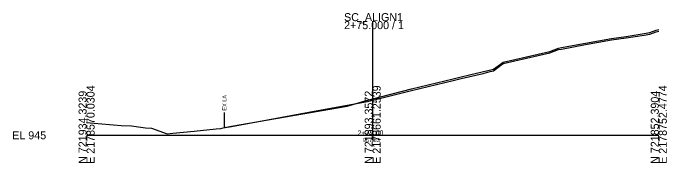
# Model space of a CAD drawing. Extents: x -2342 to 14913, y -10 to 5257.
# Drawn here: x 974.3 to 1202.8, y 490.3 to 542.8 of the extents above; entities that cross this region are included whole.
import ezdxf

# ---------------------------------------------------------------- set-up
doc = ezdxf.new("R2010")
doc.units = 0
for name, color, linetype in [('Default', 7, 'Continuous'), ('GK_Cells', 7, 'Continuous'), ('RW_X_Esmt_LA', 7, 'Continuous'), ('SC_Scratch1', 7, 'Continuous'), ('XS_P_Annotation', 7, 'Continuous'), ('XS_X_Ground_Line', 7, 'Continuous')]:
    doc.layers.add(name, color=color, linetype=linetype)

msp = doc.modelspace()

# ---------------------------------------------------------------- linework, layer by layer
at = {"layer": 'Default'}
msp.add_line((1048.2, 502.94), (1048.2, 502.69), dxfattribs=at)
at = {"layer": 'GK_Cells'}
for p, q in [((1100, 500), (1100, 540)), ((1000, 500), (1100, 500)), ((1100, 500), (1200, 500))]:
    msp.add_line(p, q, dxfattribs=at)
at = {"layer": 'RW_X_Esmt_LA'}
msp.add_line((1048.2, 502.94), (1048.2, 507.94), dxfattribs=at)
at = {"layer": 'SC_Scratch1'}
msp.add_lwpolyline([(1000, 504.49), (1003.92, 504.15), (1009.38, 503.69), (1012.09, 503.41), (1015.7, 503.27), (1020.63, 502.56), (1022.72, 502.51), (1028.16, 500.57), (1030.18, 500.74), (1037.65, 501.48), (1045.29, 502.21), (1046.79, 502.41), (1046.93, 502.43), (1047.79, 502.6), (1050.66, 503.11), (1080.82, 508.69), (1098.2, 511.83), (1100, 512.32), (1113.53, 515.73), (1128.09, 519.24), (1130.88, 519.92), (1138.57, 521.68), (1141.11, 522.37), (1142.18, 522.62), (1144.75, 524.57), (1145.59, 525.17), (1161.86, 528.87), (1164.98, 530.02), (1165.94, 530.23), (1174.38, 531.81), (1183.51, 533.42), (1188.58, 534.12), (1194.85, 535.12), (1196.82, 535.47), (1199.08, 536.29), (1200, 536.51)], dxfattribs=at)
at = {"layer": 'XS_X_Ground_Line'}
msp.add_lwpolyline([(1000, 504.49), (1003.92, 504.15), (1009.38, 503.69), (1012.09, 503.41), (1015.7, 503.27), (1020.63, 502.56), (1022.72, 502.51), (1028.16, 500.57), (1030.18, 500.74), (1037.65, 501.48), (1045.29, 502.21), (1046.79, 502.41), (1046.93, 502.43), (1047.79, 502.61), (1050.66, 503.15), (1091.04, 510.26), (1098.2, 512.34), (1098.32, 512.36), (1100, 512.83), (1113.53, 516.24), (1128.09, 519.75), (1130.88, 520.43), (1133.86, 521.22), (1142.18, 523.13), (1144.62, 524.98), (1145.59, 525.68), (1161.86, 529.38), (1164.98, 530.53), (1165.94, 530.74), (1174.38, 532.32), (1183.51, 533.93), (1188.58, 534.63), (1194.85, 535.63), (1196.82, 535.98), (1199.08, 536.8), (1200, 537.02)], dxfattribs=at)

# ---------------------------------------------------------------- texts
at = {"layer": 'Default'}
msp.add_text('-', height=0.0001, dxfattribs=at).set_placement((1000, 500))
at = {"layer": 'GK_Cells'}
for s, p in [('SC_ALIGN1', (1090, 540)), ('2+75.000 / 1', (1090, 537.2)), ('EL 945', (974, 498.6))]:
    msp.add_text(s, height=2.8, dxfattribs=at).set_placement(p)
for s, p in [('E 2178570.0304', (1002.8, 490)), ('E 2178661.2539', (1102.8, 490)), ('E 2178752.4774', (1202.8, 490)), ('N 721934.3239', (1000, 490)), ('N 721893.3572', (1100, 490)), ('N 721852.3904', (1200, 490))]:
    msp.add_text(s, height=2.8, rotation=90, dxfattribs=at).set_placement(p)
at = {"layer": 'RW_X_Esmt_LA'}
msp.add_text('EX LA', height=1.4, rotation=90, dxfattribs=at).set_placement((1048.9, 508.64))
at = {"layer": 'SC_Scratch1'}
msp.add_text('X', height=0.0001, dxfattribs=at).set_placement((1100, 512.83))
at = {"layer": 'XS_P_Annotation'}
for s, height, p in [('2+75.00', 1.8, (1094.68, 499.93)), ('957.83', 1.4, (1096.58, 497.63))]:
    msp.add_text(s, height=height, dxfattribs=at).set_placement(p)

doc.saveas('drawing.dxf')
